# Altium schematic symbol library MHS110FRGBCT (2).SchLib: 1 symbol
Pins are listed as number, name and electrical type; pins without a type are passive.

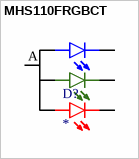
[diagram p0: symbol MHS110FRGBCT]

## MHS110FRGBCT
designator D?
RAVE RAVE RAVE / COMMON ANODE
footprint MHS110FRGBCT
pins: A, B, G, R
